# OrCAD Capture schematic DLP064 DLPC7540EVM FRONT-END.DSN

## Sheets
1 P05 - IMPORTANT NOTICE: rev: A.0
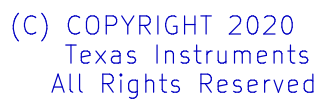
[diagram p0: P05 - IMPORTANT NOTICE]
2 P01 - TITLE
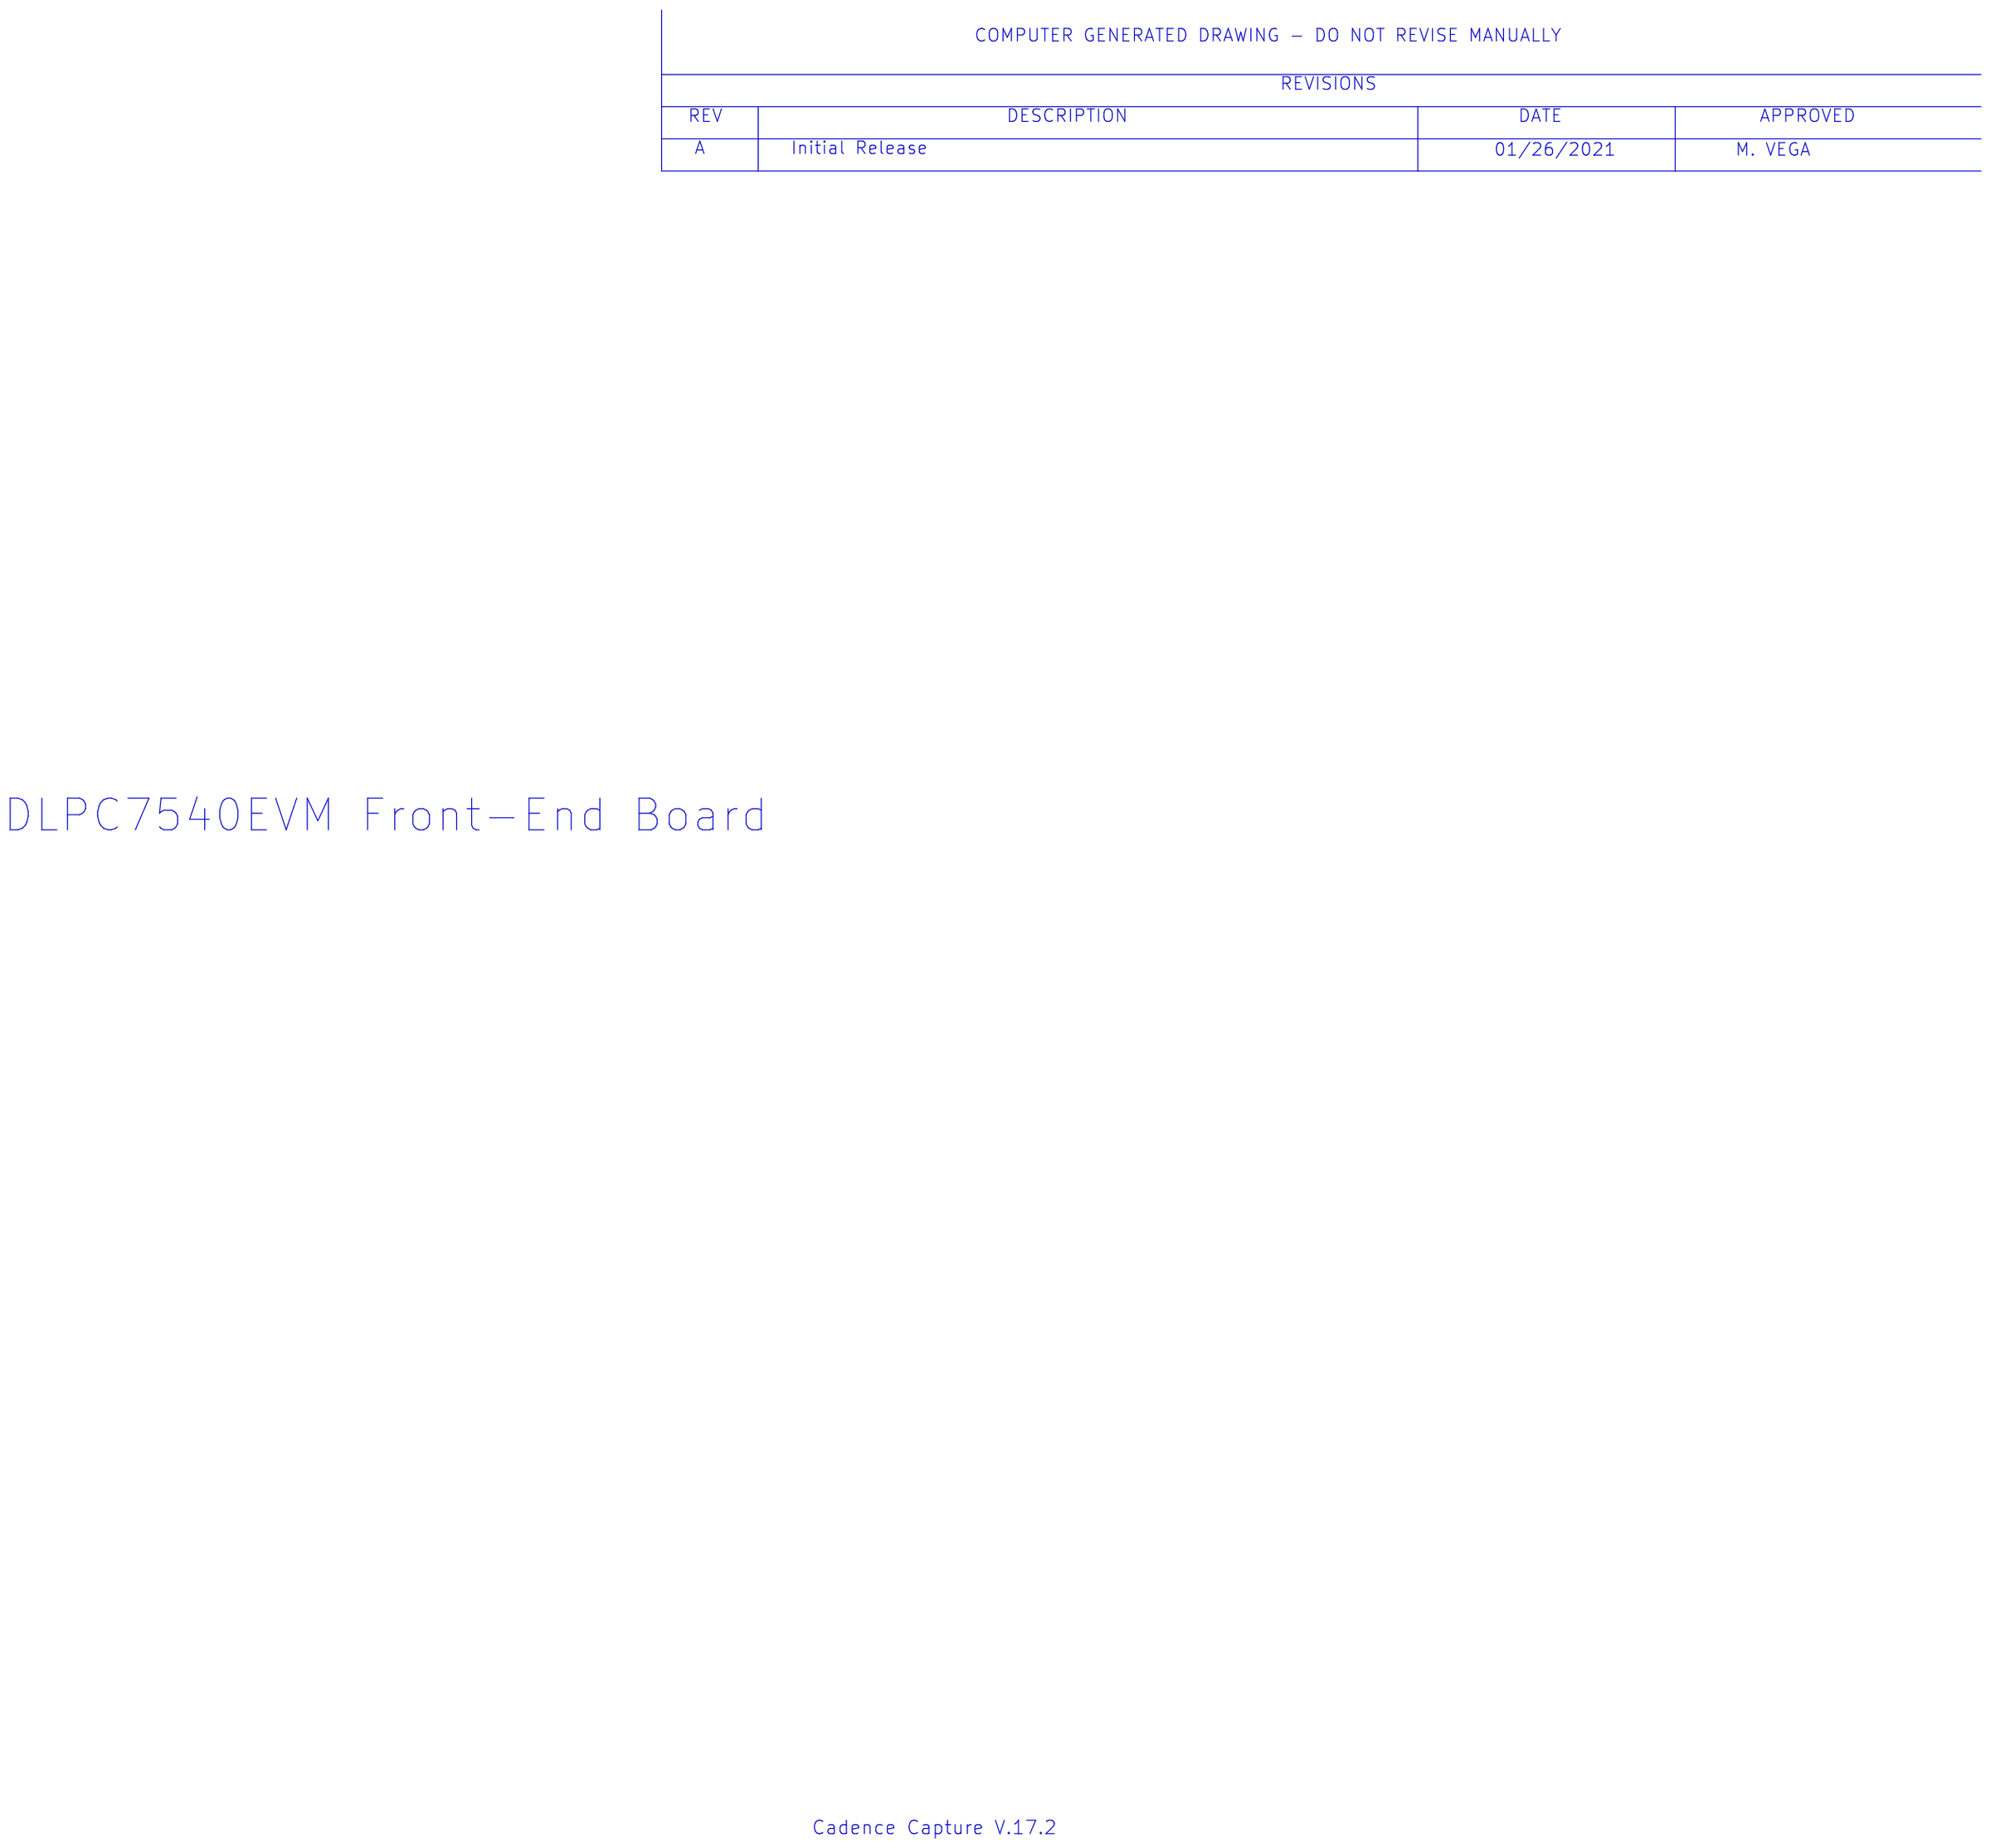
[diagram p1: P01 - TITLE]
3 P02 - IT6807: size A3
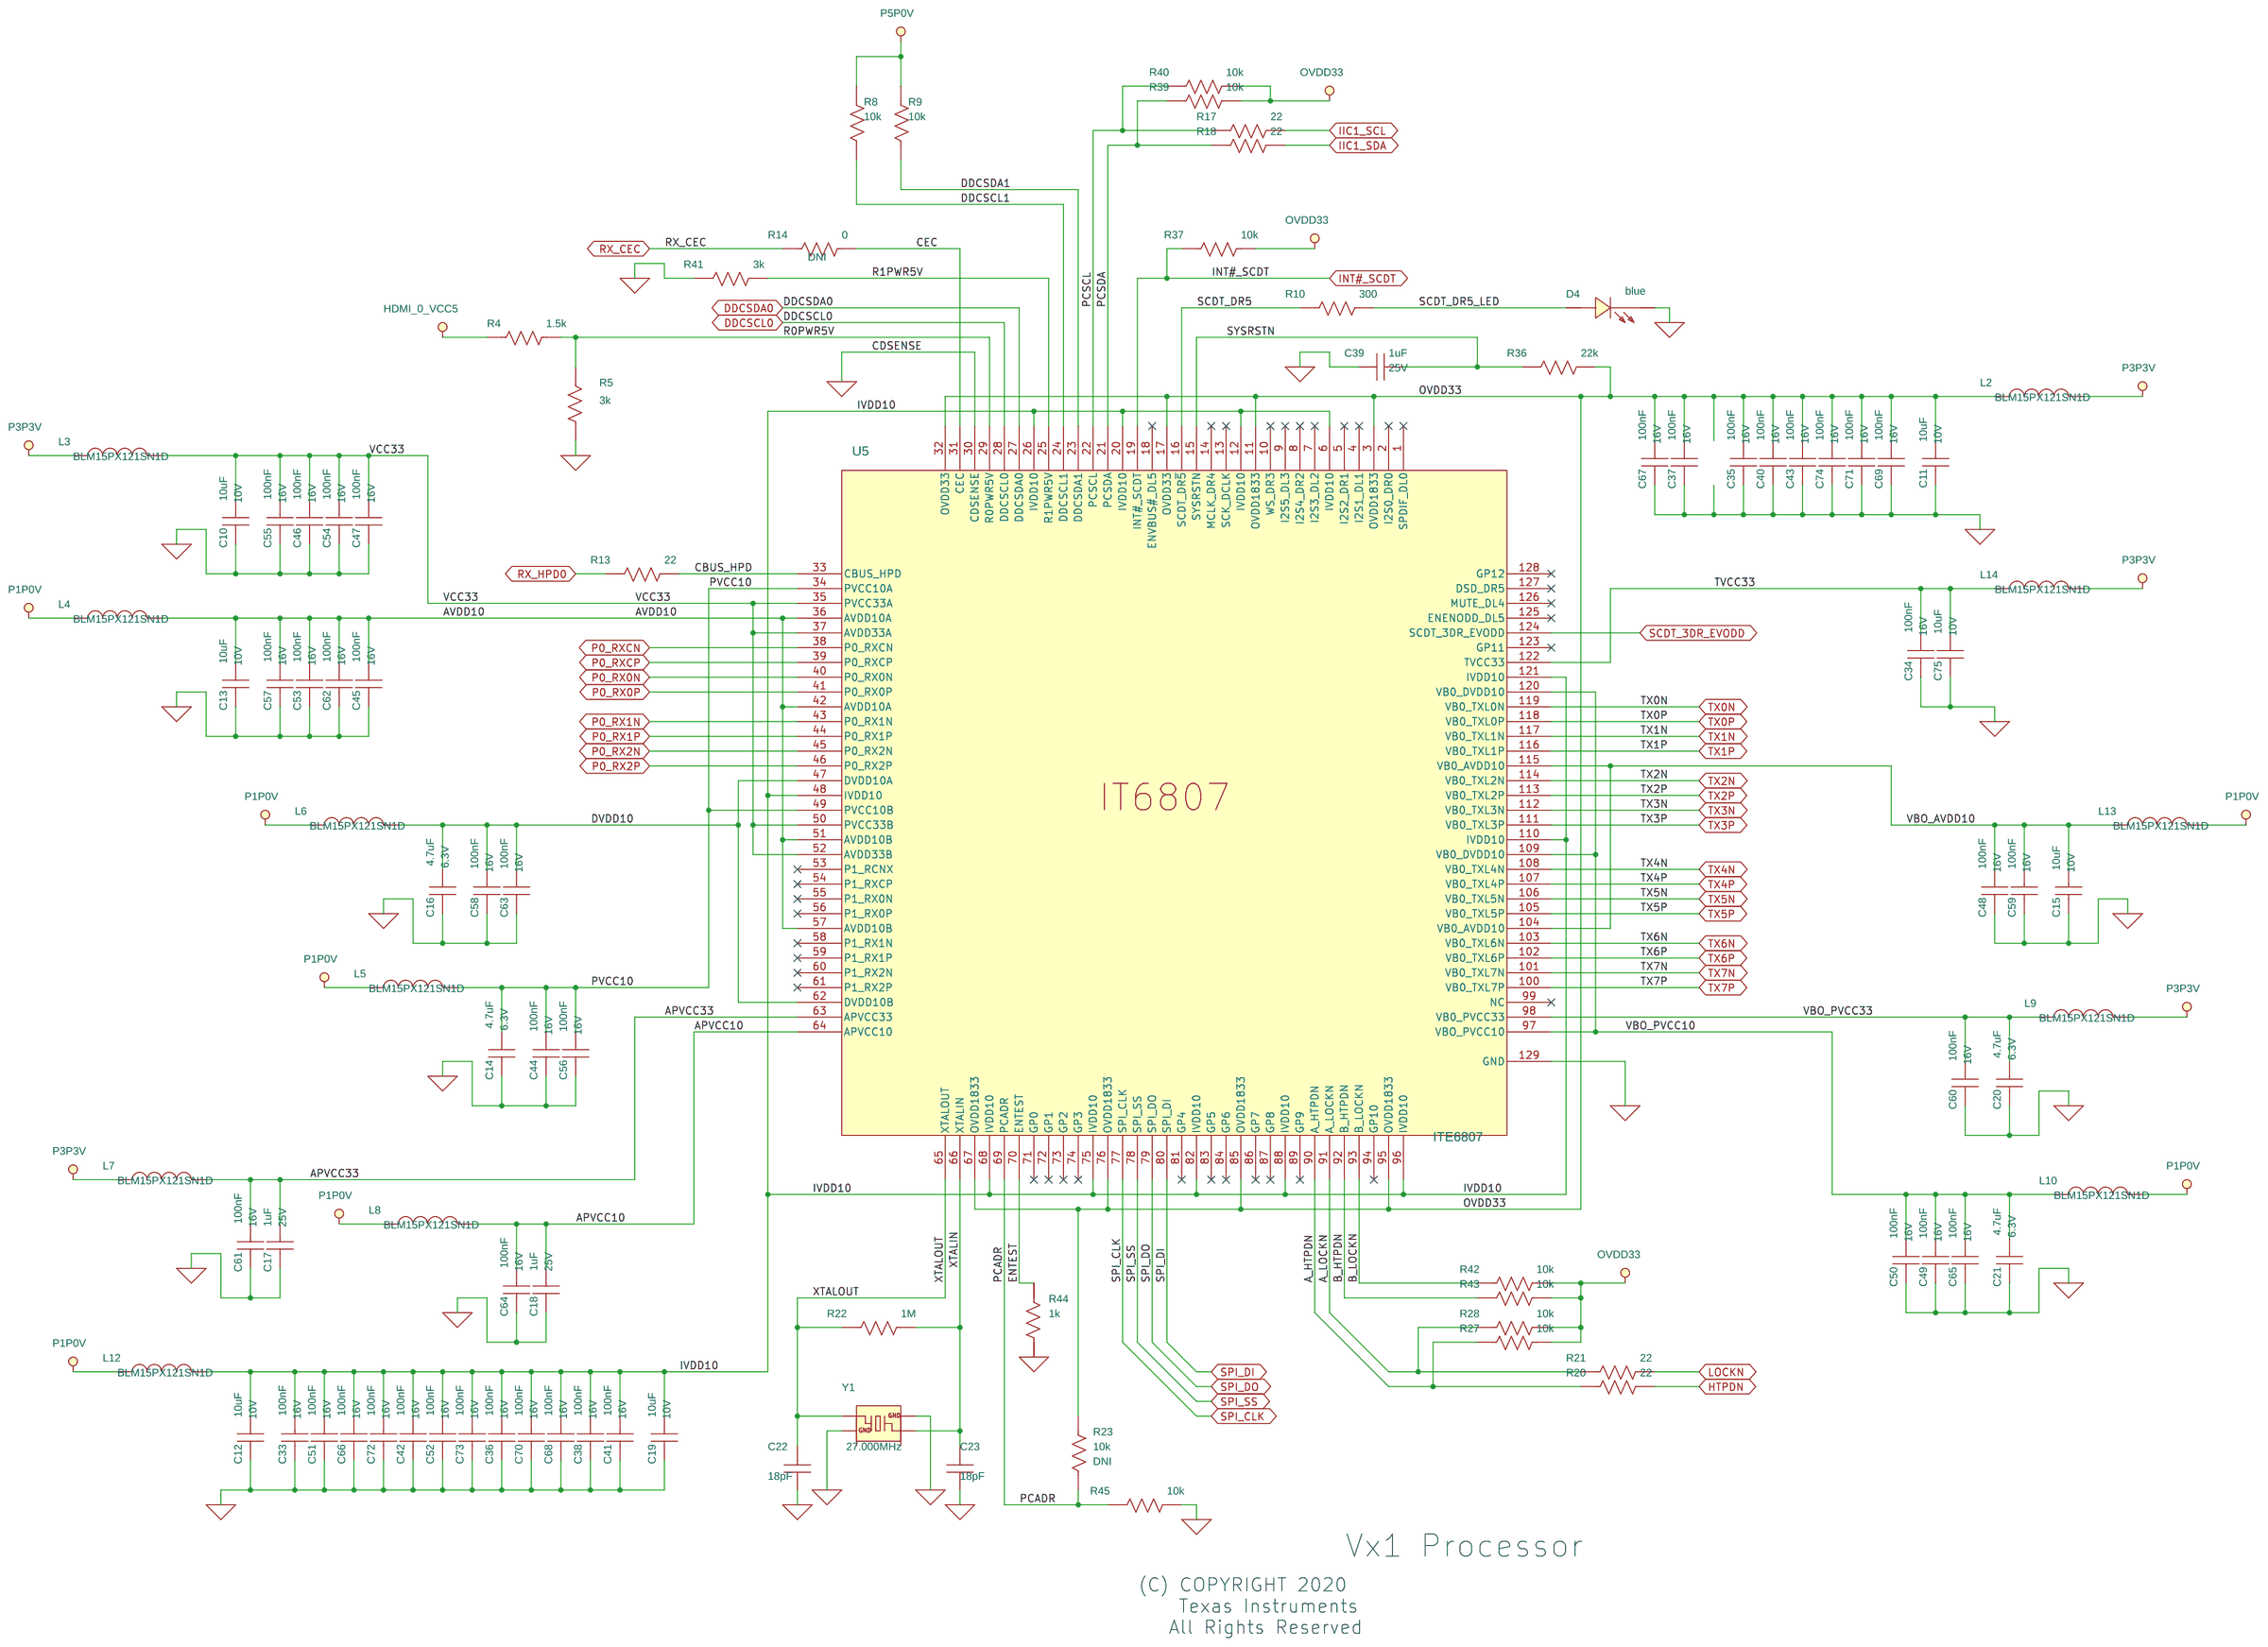
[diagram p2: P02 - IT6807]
4 P03 - HDMI & Vx1 Connection: size A3
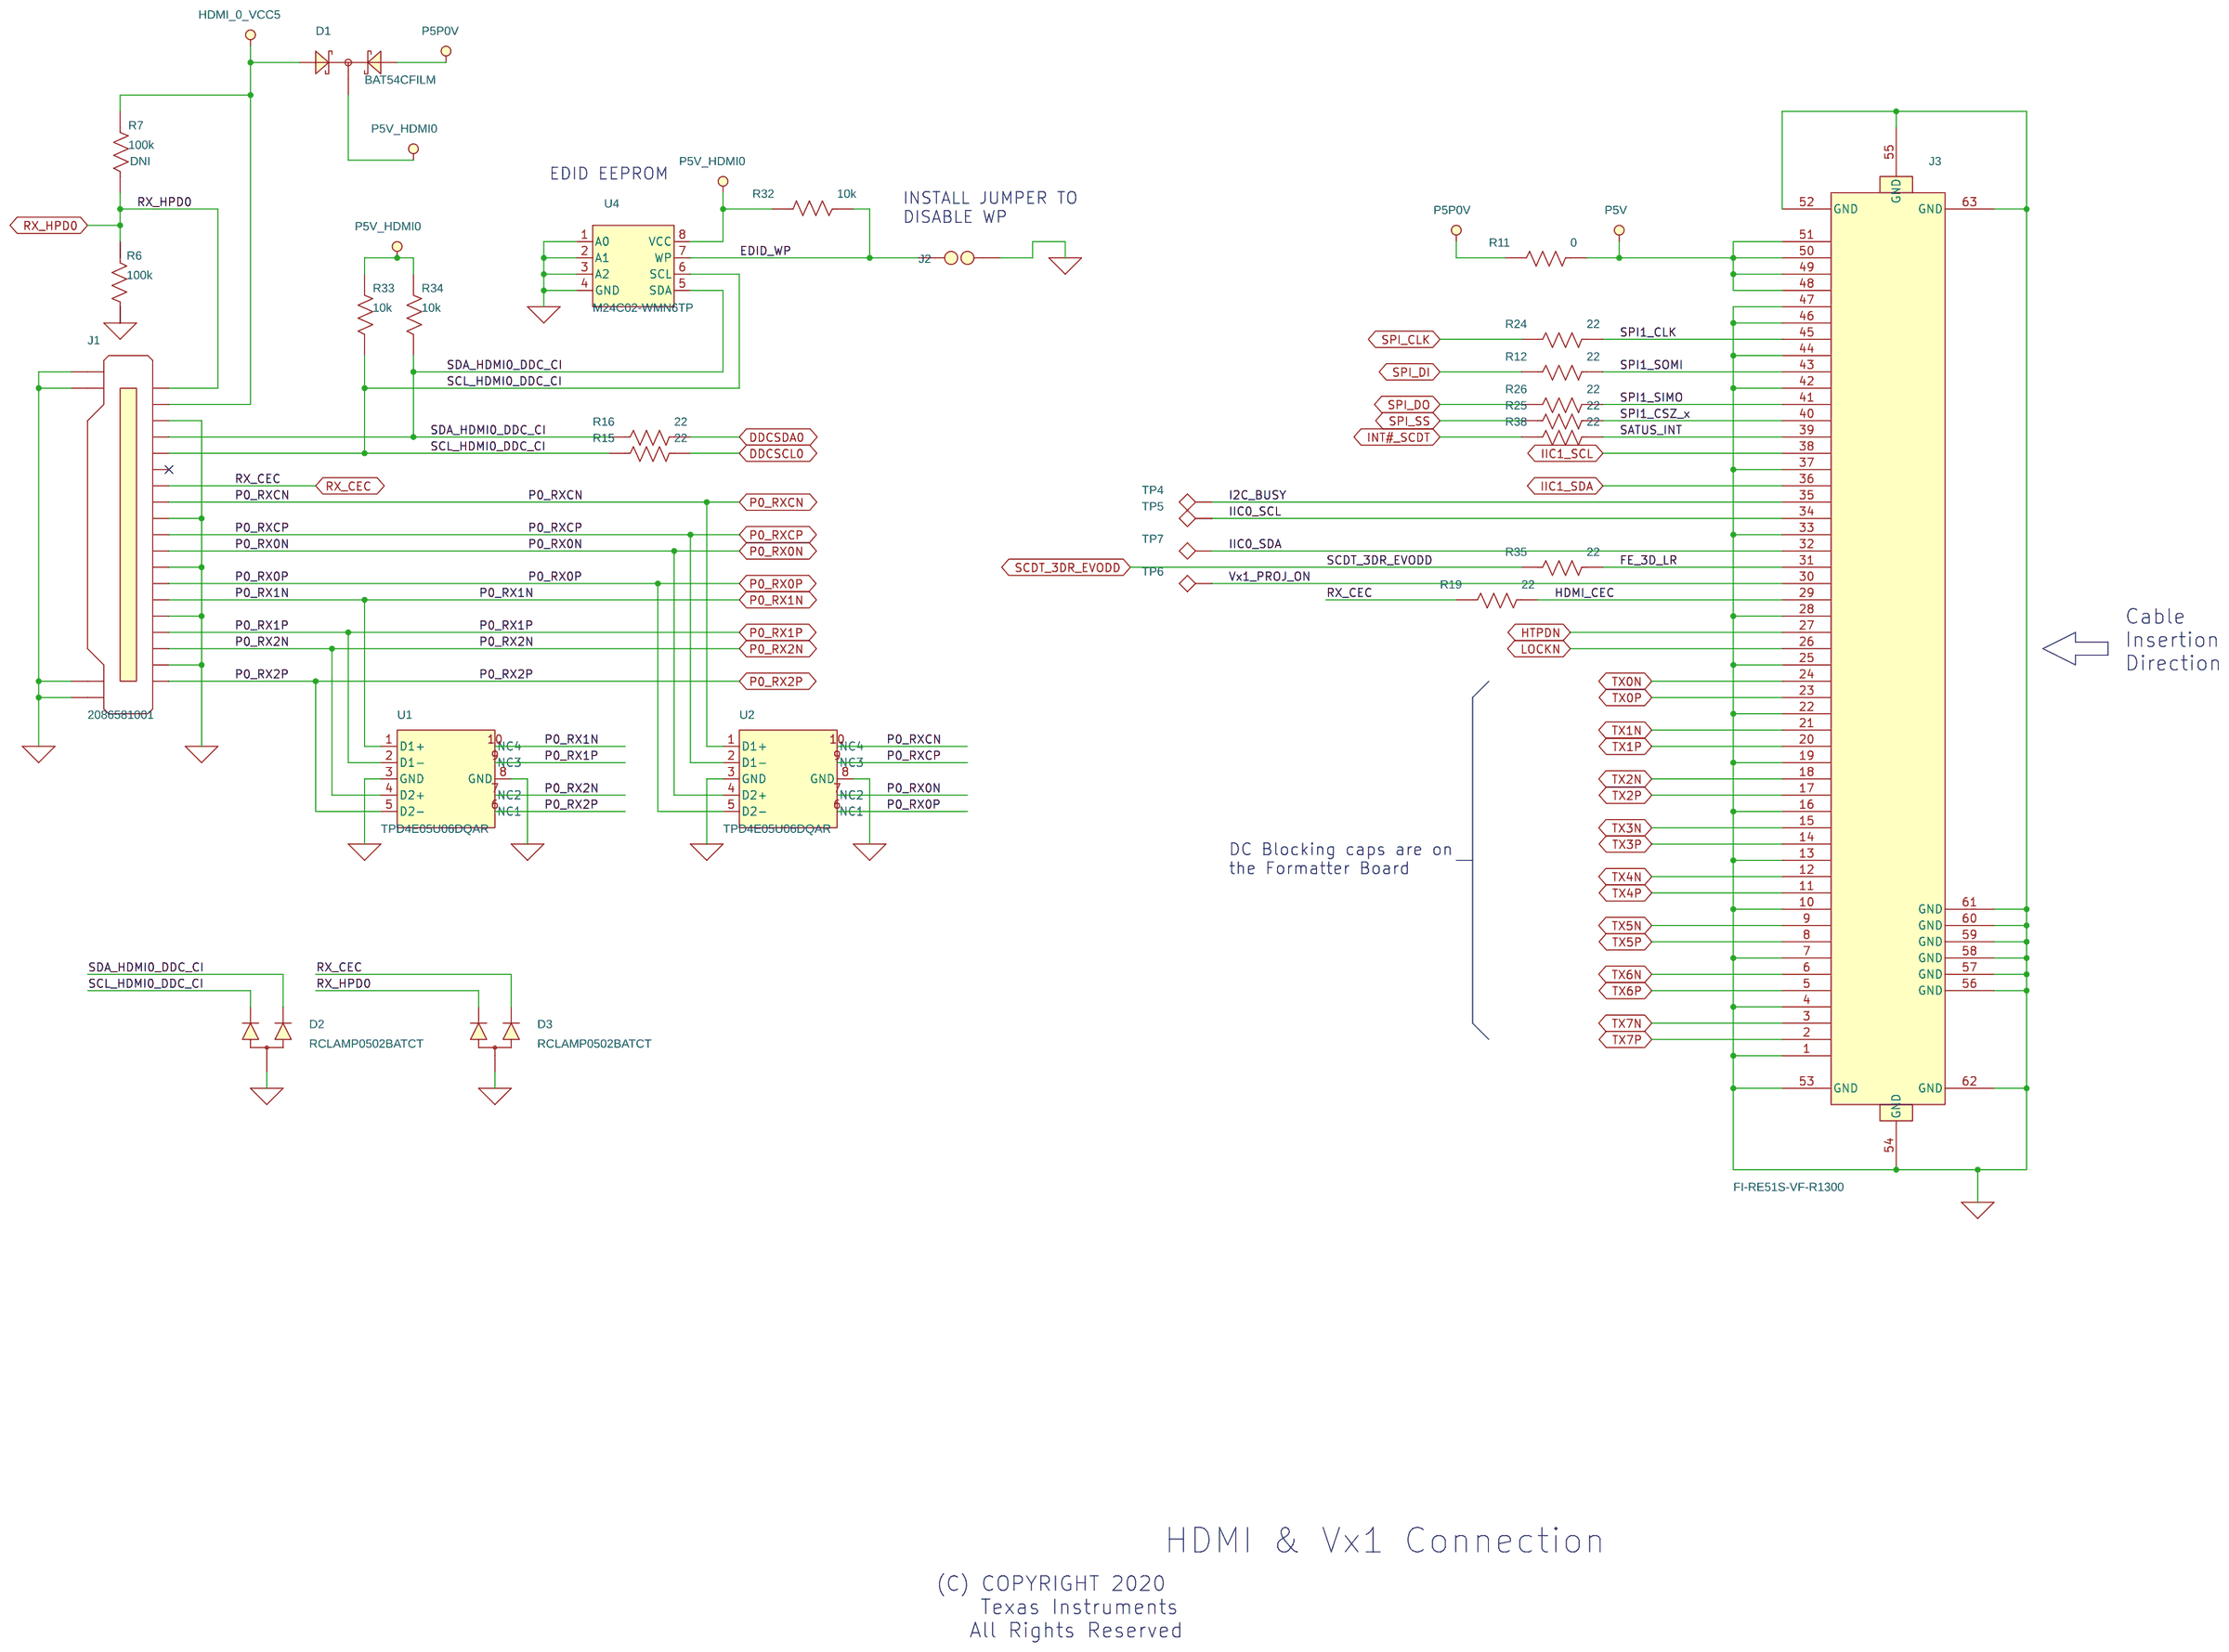
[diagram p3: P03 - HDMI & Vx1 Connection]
5 P04 - POWER: size A3
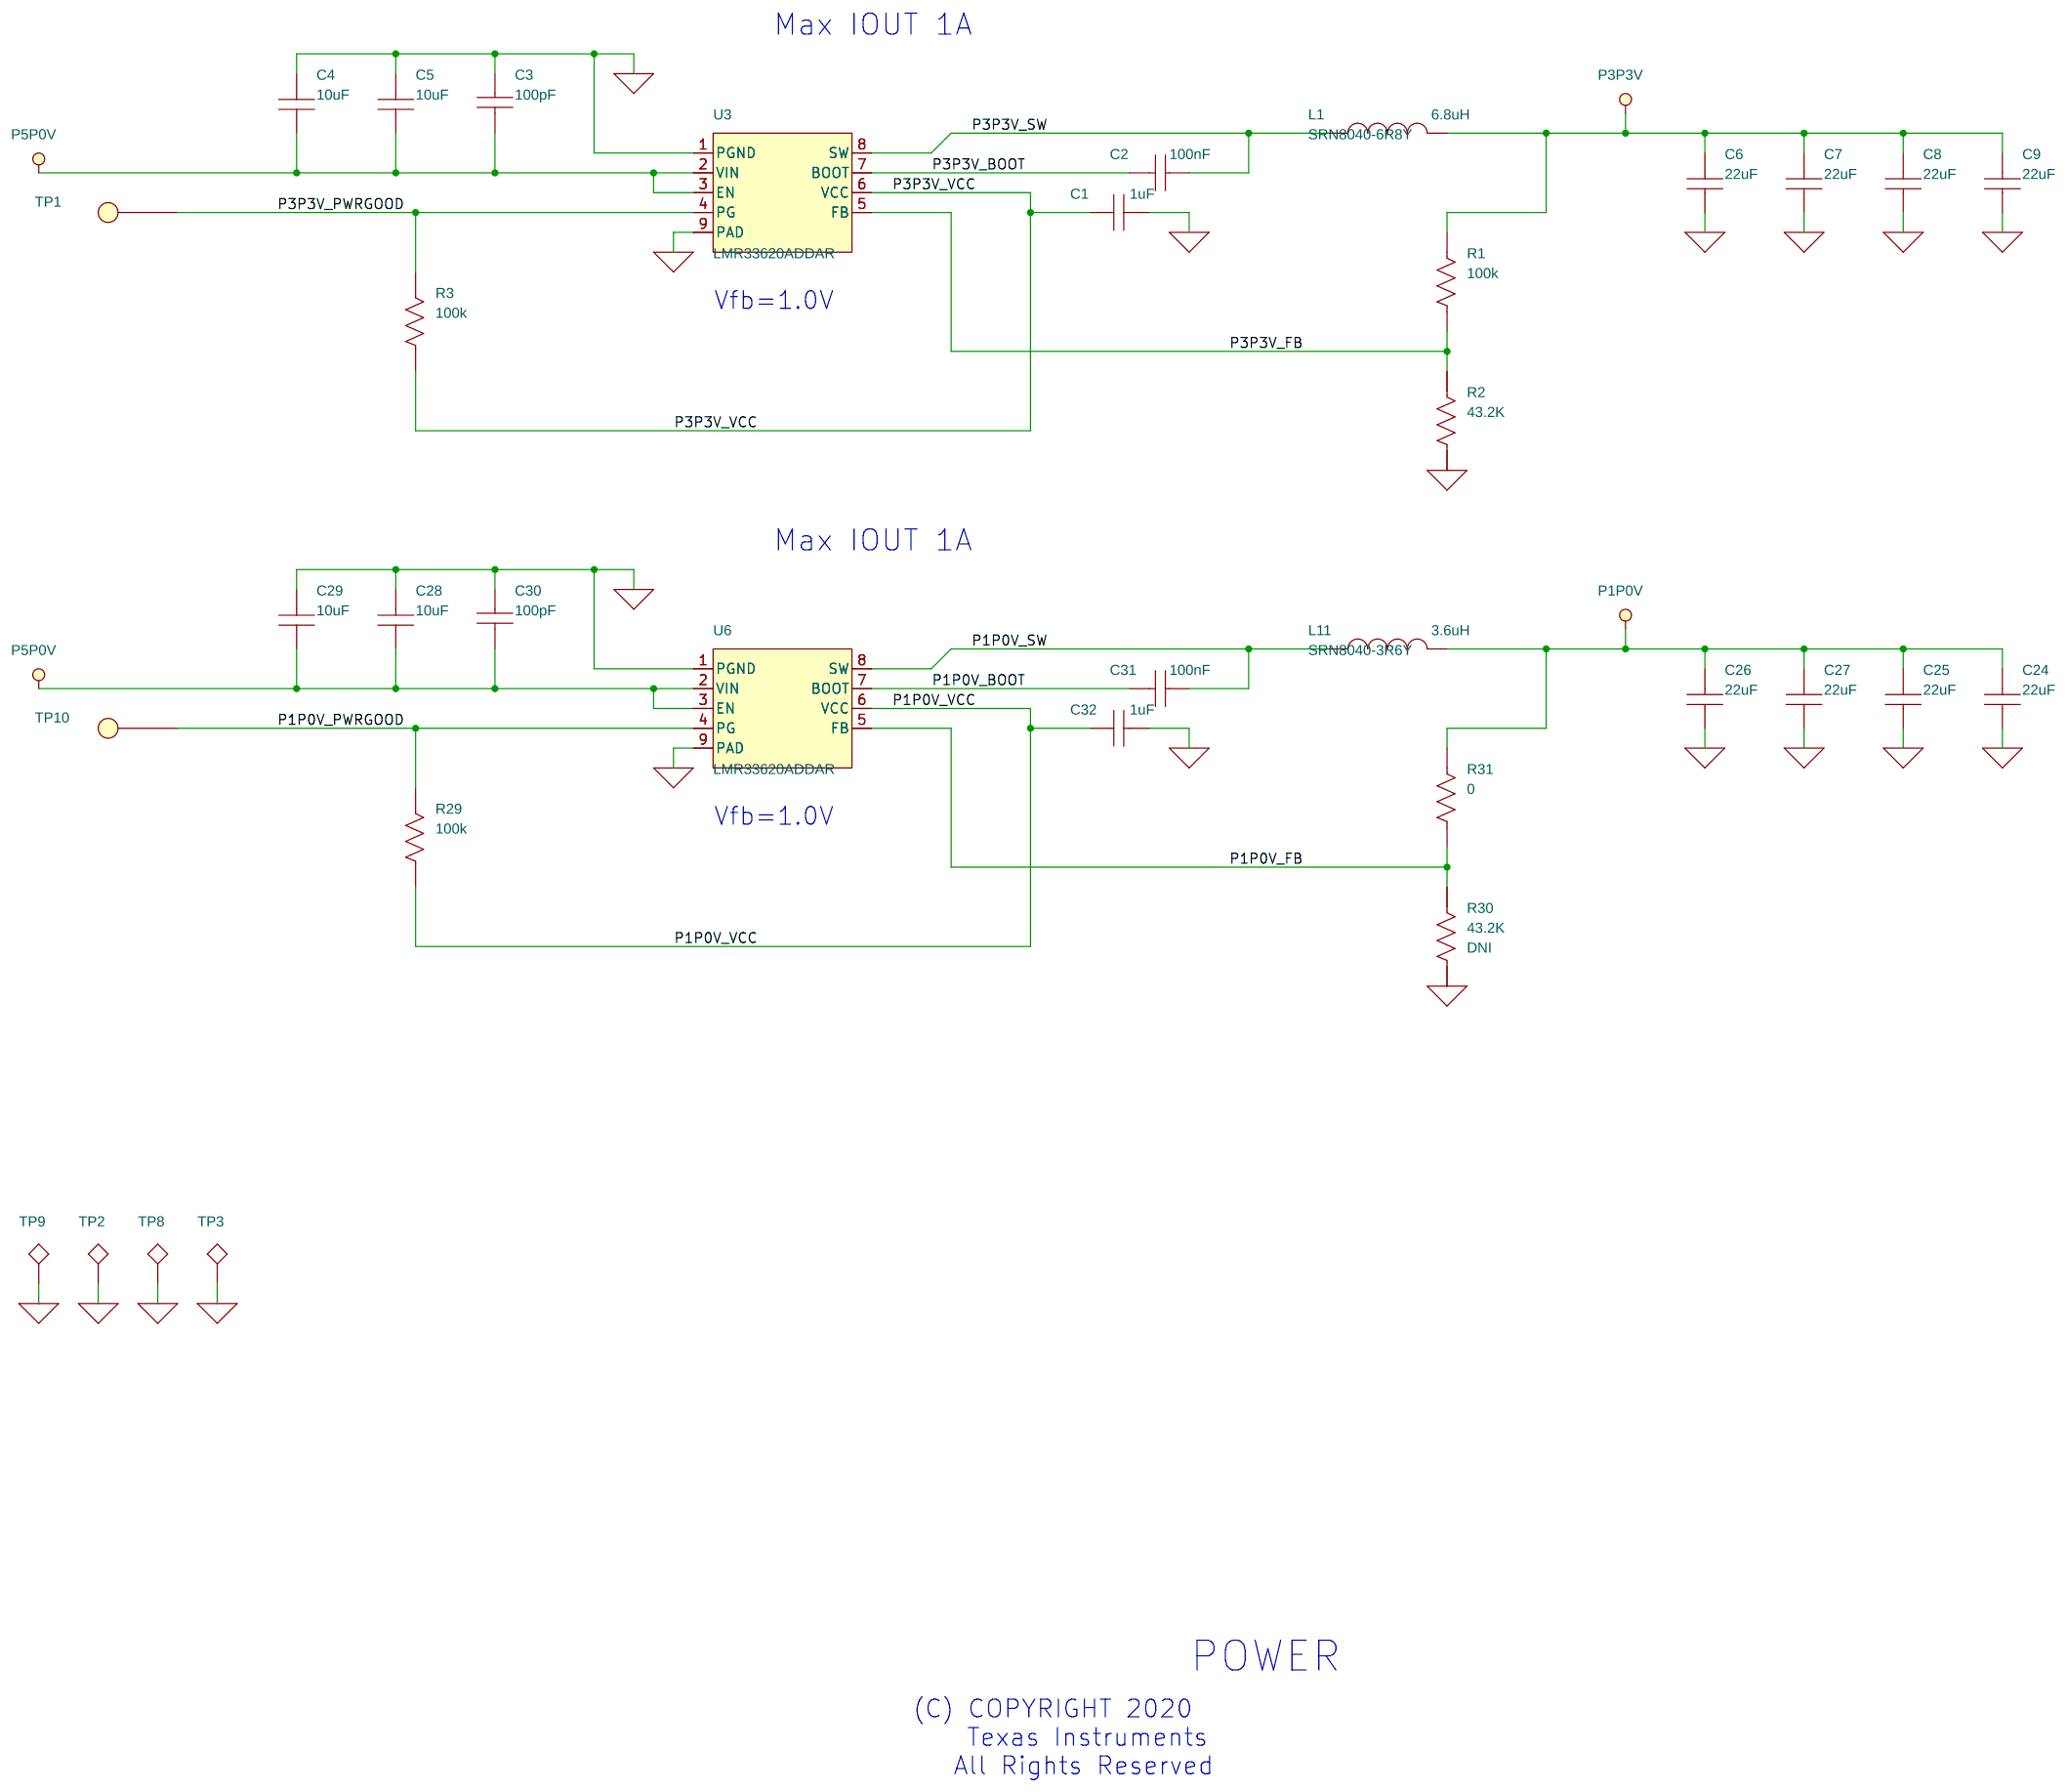
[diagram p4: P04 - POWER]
6 P06 - REVISIONS
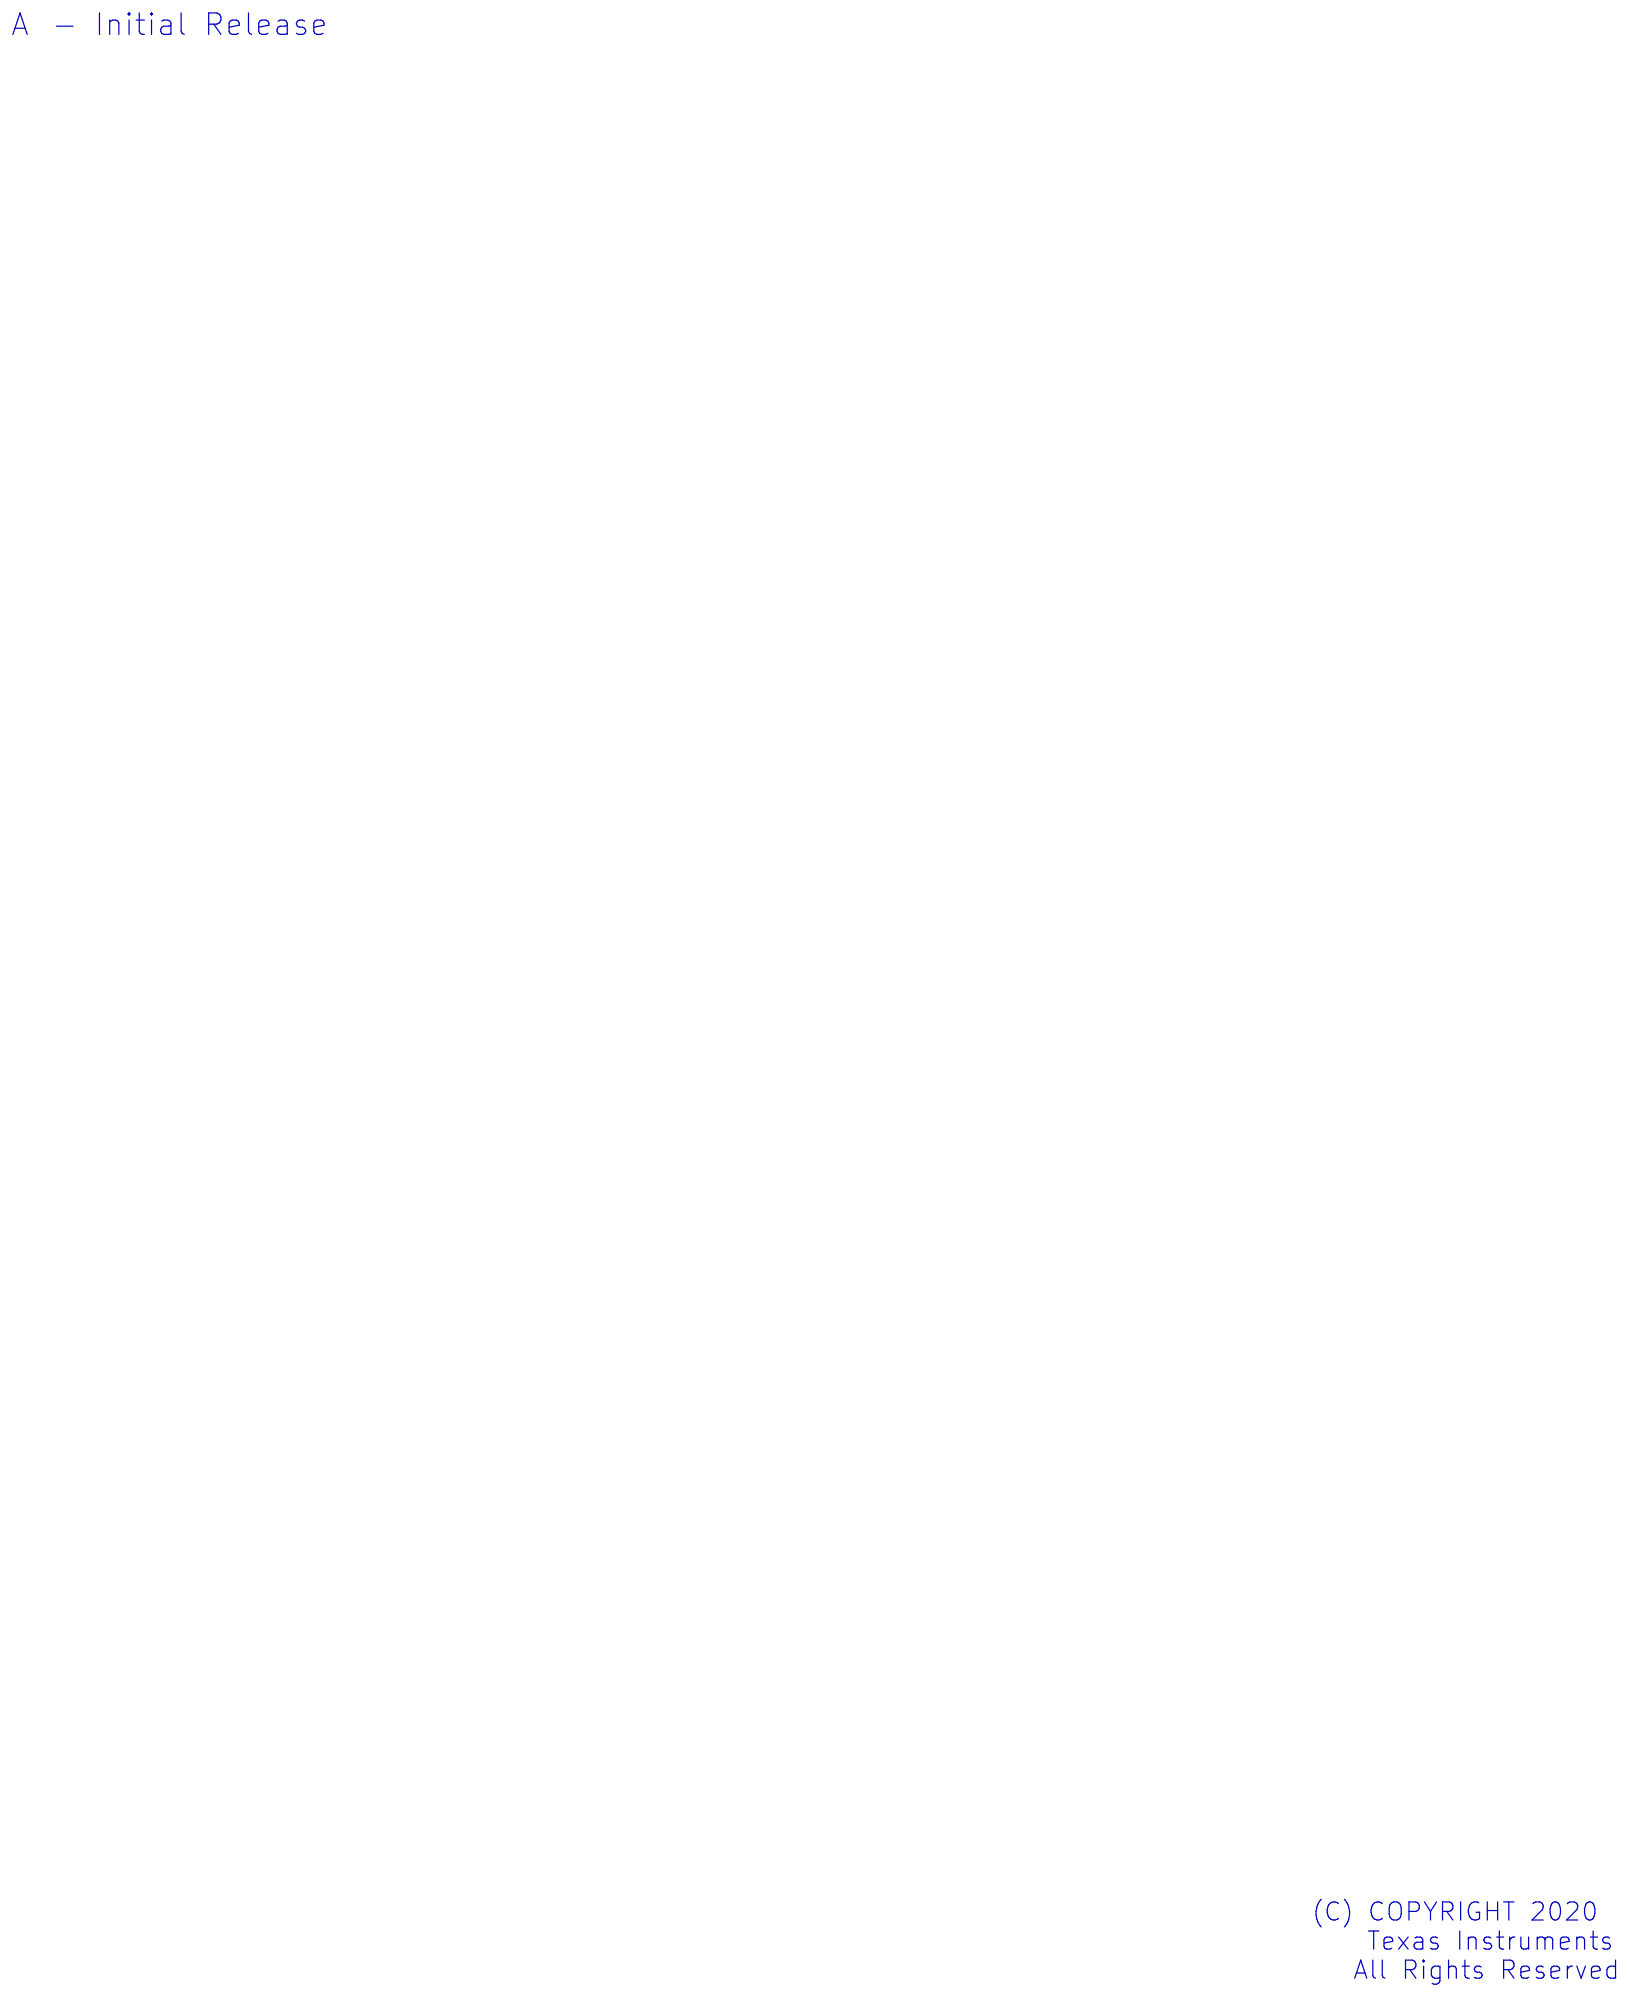
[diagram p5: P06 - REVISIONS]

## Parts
sheet P02 - IT6807
C10  10uF  [0603]
C11  10uF  [0603]
C12  10uF  [0603]
C13  10uF  [0603]
C14  4.7uF  [0402]
C15  10uF  [0603]
C16  4.7uF  [0402]
C17  1uF  [0402]
C18  1uF  [0402]
C19  10uF  [0603]
C20  4.7uF  [0402]
C21  4.7uF  [0402]
C22  18pF  [0402]
C23  18pF  [0402]
C33  100nF  [0402]
C34  100nF  [0402]
C35  100nF  [0402]
C36  100nF  [0402]
C37  100nF  [0402]
C38  100nF  [0402]
C39  1uF  [0402]
C40  100nF  [0402]
C41  100nF  [0402]
C42  100nF  [0402]
C43  100nF  [0402]
C44  100nF  [0402]
C45  100nF  [0402]
C46  100nF  [0402]
C47  100nF  [0402]
C48  100nF  [0402]
C49  100nF  [0402]
C50  100nF  [0402]
C51  100nF  [0402]
C52  100nF  [0402]
C53  100nF  [0402]
C54  100nF  [0402]
C55  100nF  [0402]
C56  100nF  [0402]
C57  100nF  [0402]
C58  100nF  [0402]
C59  100nF  [0402]
C60  100nF  [0402]
C61  100nF  [0402]
C62  100nF  [0402]
C63  100nF  [0402]
C64  100nF  [0402]
C65  100nF  [0402]
C66  100nF  [0402]
C67  100nF  [0402]
C68  100nF  [0402]
C69  100nF  [0402]
C70  100nF  [0402]
C71  100nF  [0402]
C72  100nF  [0402]
C73  100nF  [0402]
C74  100nF  [0402]
C75  10uF  [0603]
D4  blue  [LED-LTST-C190_LITEON]
L2  BLM15PX121SN1D  [0402]
L3  BLM15PX121SN1D  [0402]
L4  BLM15PX121SN1D  [0402]
L5  BLM15PX121SN1D  [0402]
L6  BLM15PX121SN1D  [0402]
L7  BLM15PX121SN1D  [0402]
L8  BLM15PX121SN1D  [0402]
L9  BLM15PX121SN1D  [0402]
L10  BLM15PX121SN1D  [0402]
L12  BLM15PX121SN1D  [0402]
L13  BLM15PX121SN1D  [0402]
L14  BLM15PX121SN1D  [0402]
R4  1.5k  [0402]
R5  3k  [0402]
R8  10k  [0402]
R9  10k  [0402]
R10  300  [0402]
R13  22  [0402]
R14  0  [0402]
R17  22  [0402]
R18  22  [0402]
R20  22  [0402]
R21  22  [0402]
R22  1M  [0402]
R23  10k  [0402]
R27  10k  [0402]
R28  10k  [0402]
R36  22k  [0402]
R37  10k  [0402]
R39  10k  [0402]
R40  10k  [0402]
R41  3k  [0402]
R42  10k  [0402]
R43  10k  [0402]
R44  1k  [0402]
R45  10k  [0402]
U5  ITE6807  [ITE6807_LQFP128]
Y1  27.000MHz  [Abracon_ABM8]
sheet P03 - HDMI & Vx1 Connection
D1  BAT54CFILM  [SOT-23-BAT54S_ST]
D2  RCLAMP0502BATCT  [Semtech_SC-75_SOT523]
D3  RCLAMP0502BATCT  [Semtech_SC-75_SOT523]
J1  2086581001  [Molex_47151-0001]
J2  HDR,2P,1R  [HDR2P_1R]
J3  FI-RE51S-VF-R1300  [FI-R51-HF_VF_Dual]
R6  100k  [0402]
R7  100k  [0402]
R11  0  [0805]
R12  22  [0402]
R15  22  [0402]
R16  22  [0402]
R19  22  [0402]
R24  22  [0402]
R25  22  [0402]
R26  22  [0402]
R32  10k  [0402]
R33  10k  [0402]
R34  10k  [0402]
R35  22  [0402]
R38  22  [0402]
TP4  TP_WHT  [TP_Keystone_5011]
TP5  TP_WHT  [TP_Keystone_5011]
TP6  TP_WHT  [TP_Keystone_5011]
TP7  TP_WHT  [TP_Keystone_5011]
U1  TPD4E05U06DQAR  [TPD4E05U06DQAR_USON10]
U2  TPD4E05U06DQAR  [TPD4E05U06DQAR_USON10]
U4  M24C02-WMN6TP  [SOIC-8_3p90mm_wide]
sheet P04 - POWER
C1  1uF  [0402]
C2  100nF  [0402]
C3  100pF  [0402]
C4  10uF  [1210]
C5  10uF  [1210]
C6  22uF  [0805]
C7  22uF  [0805]
C8  22uF  [0805]
C9  22uF  [0805]
C24  22uF  [0805]
C25  22uF  [0805]
C26  22uF  [0805]
C27  22uF  [0805]
C28  10uF  [1210]
C29  10uF  [1210]
C30  100pF  [0402]
C31  100nF  [0402]
C32  1uF  [0402]
L1  6.8uH  [Bourns_SRN8040]
L11  3.6uH  [Bourns_SRN8040]
R1  100k  [0402]
R2  43.2K  [0402]
R3  100k  [0402]
R29  100k  [0402]
R30  43.2K  [0402]
R31  0  [0402]
TP1  TP_WHT  [TP_Keystone_5011]
TP2  TP_BLK  [TP_Keystone_5011]
TP3  TP_BLK  [TP_Keystone_5011]
TP8  TP_BLK  [TP_Keystone_5011]
TP9  TP_BLK  [TP_Keystone_5011]
TP10  TP_WHT  [TP_Keystone_5011]
U3  LMR33620ADDAR  [HSOIC8_DDA0008J]
U6  LMR33620ADDAR  [HSOIC8_DDA0008J]

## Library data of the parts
C10-C13 C15 C19 C75 = PAS,CAP,NP: CCA: 34; DigiKey: 445-6853-1-ND; Family: passive; Index PN: 1207; Install: Y; Lead Style: SMT; MFG: TDK; P/D_NUM: C1608X5R1A106M080AC; Part Number: C1608X5R1A106M080AC; Part Specific: CAP CER 10UF 10V 20% X5R 0603; TOLERANCE: 20%; Type: capacitor; VPC: 10V; Vendor: TDK
C14 C16 C20 C21 = PAS,CAP,NP: ALT_SYMBOLS: 0402_1mm; DigiKey: 490-5915-1-ND; Family: passive; Index PN: 1389; Lead Style: SMT; MFG: Murata; Material: x5r; P/D_NUM: GRM155R60J475ME47D; Part Number: GRM155R60J475ME47D; Part Specific: CAP CER 4.7UF 6.3V 20% X5R 0402; Tolerance: 20%; VPC: 6.3V; Vendor: Murata
C1 C17 C18 C32 C39 = PAS,CAP,NP: ALT_SYMBOLS: 0402_1mm; DigiKey: 1276-1445-1-ND; Family: passive; Index PN: 1278; Lead Style: SMT; MFG: Samsung; P/D_NUM: CL05A105KA5NQNC; Part Number: CL05A105KA5NQNC; Part Specific: CAP CER 1UF 25V 20% X5R 0402; Tolerance: 20%; VPC: 25V; Vendor: Samsung
C22 C23 = PAS,CAP,NP: ALT_SYMBOLS: 0402_1mm; DigiKey: 311-1415-1-ND; Family: passive; Lead Style: SMT; MFG: Yageo; Material: npo; P/D_NUM: CC0402JRNPO9BN180; Part Number: CC0402JRNPO9BN180; Part Specific: CAP CER 18PF 50V C0G 5% 0402; Tolerance: 5%; VPC: 50V; Vendor: Yageo; Voltage: 50V
C33-C38 C40-C74 = PAS,CAP,NP: ALT_SYMBOLS: 0402_1mm; DigiKey: 1276-1001-1-ND; Family: passive; Index PN: 681; Lead Style: SMT; MFG: Samsung; Material: x7r; P/D_NUM: CL05B104KO5NNNC; Part Number: CL05B104KO5NNNC; Part Specific: CAP CER .1UF 16V X7R 0402; Tolerance: 10%; VPC: 16V; Vendor: Samsung
D4 = PAS,DIODE,LED,ALT: DigiKey: 160-1647-1-ND; Family: passive; Index PN: 1728; Install: Y; Lead Style: SMT; MFG: Liteon; P/D_NUM: LTST-C191TBKT; Part Number: LTST-C191TBKT; Part Specific: LED BLUE CLEAR CHIP SMD; Type: diode,led; Vendor: Liteon
L2-L10 L12-L14 = PAS,INDUCTOR: ALT_SYMBOLS: 0402_1mm; DigiKey: 490-9656-1-ND; Family: passive; Index PN: 1670; Lead Style: SMT; MFG: Murata; Part Specific: FERRITE BEAD 120 OHM 0402 2A 50Ohm DC; Type: ferrite bead; VPC: 2000mA; Vendor: Murata
R4 = PAS,R,large: ALT_SYMBOLS: 0402_1mm; DigiKey: P1.50KLCT-ND; Family: passive; Index PN: 1117; Lead Style: SMT; MFG: Panasonic; Material: chip; P/D_NUM: ERJ-2RKF1501X; Part Number: ERJ-2RKF1501X; Part Specific: RES 1.50K OHM 1/10W 1% 0402 SMD; Tolerance: 1%; Type: resistor; Vendor: Panasonic
R5 R41 = PAS,R,large: ALT_SYMBOLS: 0402_1mm; DigiKey: P3.00KLCT-ND; Family: passive; Index PN: 1230; Lead Style: SMT; MFG: Panasonic; P/D_NUM: ERJ-2RKF3001X; Part Number: ERJ-2RKF3001X; Part Specific: RES 3K OHM 1/10W 1% 0402 SMD; Tolerance: 1%; Type: resistor; Vendor: Panasonic
R8 R9 R27 R28 R32-R34 R37 R39 R40 R42 R43 R45 = PAS,R,large: ALT_SYMBOLS: 0402_1mm; DigiKey: 311-10.0KLRCT-ND; Family: passive; Index PN: 680; Lead Style: SMT; MFG: Yageo; Material: chip; P/D_NUM: RC0402FR-0710KL; Part Number: RC0402FR-0710KL; Part Specific: RES SMD 10K OHM 1% 1/16W 0402; Power: 1/16W; Tolerance: 1%; Type: resistor; VPC: 1/16W; Vendor: Yageo
R10 = PAS,R,large: ALT_SYMBOLS: 0402_1mm; DigiKey: P300LCT-ND; Family: passive; Index PN: 1053; Lead Style: SMT; MFG: Panasonic; Material: chip; P/D_NUM: ERJ-2RKF3000X; Part Number: ERJ-2RKF3000X; Part Specific: RES 300 OHM 1/10W 1% 0402 SMD; Tolerance: 1%; Type: resistor; VPC: 1/16W; Vendor: Panasonic
R12 R13 R15-R21 R24-R26 R35 R38 = PAS,R,large: ALT_SYMBOLS: 0402_1mm; DigiKey: 311-22.0LRCT-ND; Family: passive; Index PN: 1215; Lead Style: SMT; MFG: Yageo; Material: chip; P/D_NUM: RC0402FR-0722RL; Part Number: RC0402FR-0722RL; Part Specific: RES 22.0 OHM 1/16W 1% 0402 SMD; Tolerance: 1%; Type: resistor; VPC: 1/16W; Vendor: Yageo
R14 = PAS,R,large: ALT_SYMBOLS: 0402_1mm; DigiKey: P0.0JCT-ND; Family: passive; Index PN: 687; Install: DNI; Lead Style: SMT; MFG: Panasonic; Material: chip; P/D_NUM: ERJ-2GE0R00X; Part Number: ERJ-2GE0R00X; Part Specific: RES 0.0 OHM 1/16W 0402 SMD; Power: 1/16W; Type: resistor; VPC: 1/16W; Vendor: Panasonic
R22 = PAS,R,large: ALT_SYMBOLS: 0402_1mm; DigiKey: P1.00MLCT-ND; Family: passive; Index PN: 1229; Lead Style: SMT; MFG: Panasonic; Material: chip; P/D_NUM: ERJ-2RKF1004X; Part Number: ERJ-2RKF1004X; Part Specific: RES 1M OHM 1/10W 1% 0402 SMD; Tolerance: 1%; Type: resistor; Vendor: Panasonic
R23 = PAS,R,large: ALT_SYMBOLS: 0402_1mm; DigiKey: 311-10.0KLRCT-ND; Family: passive; Index PN: 680; Install: DNI; Lead Style: SMT; MFG: Yageo; Material: chip; P/D_NUM: RC0402FR-0710KL; Part Number: RC0402FR-0710KL; Part Specific: RES SMD 10K OHM 1% 1/16W 0402; Power: 1/16W; Tolerance: 1%; Type: resistor; VPC: 1/16W; Vendor: Yageo
R36 = PAS,R,large: ALT_SYMBOLS: 0402_1mm; DigiKey: YAG4356CT-ND; Family: passive; Index PN: 1686; Lead Style: SMT; MFG: Yageo; Material: chip; P/D_NUM: RT0402BRE0722KL; Part Number: RT0402BRE0722KL; Part Specific: RES SMD 22K OHM 0.1% 1/16W 0402; Tolerance: 0.1%; Type: resistor; VPC: 1/16W; Vendor: Yageo
R44 = PAS,R,large: ALT_SYMBOLS: 0402_1mm; DigiKey: 311-1.00KLRCT-ND; Family: passive; Index PN: 684; Lead Style: SMT; MFG: Yageo; Material: chip; P/D_NUM: RC0402FR-071KL; Part Number: RC0402FR-071KL; Part Specific: RES 1.00K OHM 1/10W 1% 0402 SMD; Power: 1/16W; Tolerance: 1%; Type: resistor; VPC: 1/16W; Vendor: Yageo
U5 = INF,VIDEO,IT6807_LQFP-128_0: DigiKey: ---; Family: interface; Index PN: 1774; Lead Style: SMT; MFG: ITE Tech Inc; P/D_NUM: IT6807E; Part Number: IT6807E; Part Specific: HDMI RCVR Vx1 OUT 128LQFP; Type: video; Vendor: ITE Tech Inc
Y1 = PAS,CRYSTAL,ABM11: DigiKey: 535-9141-1-ND; Family: passive; Index PN: 1231; Lead Style: SMT; MFG: Abracon; P/D_NUM: ABM8-27.000MHZ-B2-T; Part Number: ABM8-27.000MHZ-B2-T; Part Specific: CRYSTAL 27MHZ 18PF SMD; Vendor: Abracon
D1 = PAS,DIODE,SCHOTTKY,BAT54CFILM: DigiKey: 497-3786-1-ND; Family: passive; Index PN: 1514; Lead Style: SMT; MFG: STMicroelectronics; Part Specific: DIODE ARRAY SCHOTTKY 40V SOT23-3; Type: diode,schottky; VPC: 40V; Vendor: STMicroelectronics
D2 D3 = PAS,DIODE,TVS,RClamp502b,small: DigiKey: RCLAMP0502BATCTCT-ND; Family: passive; Index PN: 1222; Lead Style: SMT; MFG: Semtech; Part Specific: TVS DIODE 5V 25V SC75; Type: diode,tvs; Vendor: Semtech
J1 = EM,CONN,HDMI,1R,x1: DigiKey: 900-2086581001CT-ND; Family: electro/mechanical; Lead Style: SMT; MFG: Molex; Part Specific: CONN RCPT HDMI V2.1 19POS SMD RA; Type: connector; Vendor: Molex
J2 = EM,JMP,2P,1R: DigiKey: 952-2261-ND; Index PN: 180; Lead Style: TH; MFG: Harwin; P/D_NUM: M20-9990245; Part Number: M20-9990245; Part Specific: CONN HEADER VERT 2POS 2.54MM; Pin Cnt: 2; Pin Spacing: 100mil; Row Cnt: 1; Type: header; Vendor: Harwin
J3 = TMP_094452: DigiKey: 670-2149-1-ND; Family: electro/mechanical; Index PN: 1629; Lead Style: SMT; MFG: JAE; Part Specific: CONN RCPT 51POS 0.02 GOLD SMD; Pin Cnt: 51; Type: connector; Vendor: JAE
R6 = PAS,R,large: ALT_SYMBOLS: 0402_1mm; DigiKey: 541-100KLCT-ND; Family: passive; Index PN: 712; Lead Style: SMT; MFG: Vishay/Dale; Material: chip; P/D_NUM: CRCW0402100KFKED; Part Number: CRCW0402100KFKED; Part Specific: RES 100K OHM 1/10W 1% 0402 SMD; Power: 1/16W; Tolerance: 1%; Type: resistor; VPC: 1/16W; Vendor: Vishay/Dale
R7 = PAS,R,large: ALT_SYMBOLS: 0402_1mm; DigiKey: 541-100KLCT-ND; Family: passive; Index PN: 712; Install: DNI; Lead Style: SMT; MFG: Vishay/Dale; Material: chip; P/D_NUM: CRCW0402100KFKED; Part Number: CRCW0402100KFKED; Part Specific: RES 100K OHM 1/10W 1% 0402 SMD; Power: 1/16W; Tolerance: 1%; Type: resistor; VPC: 1/16W; Vendor: Vishay/Dale
R11 = PAS,R,large: DigiKey: P0.0ACT-ND; Family: passive; Index PN: 160; MFG: Panasonic; Material: chip; P/D_NUM: ERJ-6GEY0R00V; Part Number: ERJ-6GEY0R00V; Part Specific: RES 0.0 OHM 1/8W 0805 SMD 2A; Power: 1/8w; Type: resistor; VPC: 2A; Vendor: Panasonic
TP4-TP7 = EM,TERM,TESTPOINT: DigiKey: 36-5012-ND; Family: electro/mechanical; Index PN: 1162; Install: DNI; Lead Style: TH; MFG: Keystone; P/D_NUM: 5012; Part Number: 5012; Part Specific: TEST POINT PC MULTI PURPOSE WHT .063inD hole; Type: terminal; Vendor: Keystone
U1 U2 = PAS,DIODE,ARRAY,TVS,TPD4E05U06: DigiKey: 296-35765-1-ND; Family: passive; Index PN: 1775; Lead Style: SMT; MFG: Texas Instruments; Part Specific: TVS DIODE 5.5V 14V 10SON; Type: diode,tvs; Vendor: Texas Instruments
U4 = MEM,EEPROM,24LCxx: DigiKey: 497-8552-1-ND; Family: memory; Index PN: 1131; Lead Style: SMT; MFG: Stmicroelectronics; Part Specific: IC EEPROM 2KBIT 400KHZ 8SOIC; Type: eeprom; Vendor: Stmicroelectronics
C2 C31 = PAS,CAP,NP: ALT_SYMBOLS: 0402_1mm; DigiKey: 587-3499-1-ND; Family: passive; Index PN: 1280; Lead Style: SMT; MFG: Taiyo Yuden; Material: x5r; P/D_NUM: UMK105BJ104KV-F; Part Number: UMK105BJ104KV-F; Part Specific: CAP CER 0.1UF 50V 10% X5R 0402; Tolerance: 10%; VPC: 50V; Vendor: Taiyo Yuden
C3 C30 = PAS,CAP,NP: ALT_SYMBOLS: 0402_1mm; DigiKey: 478-1089-1-ND; Family: passive; Index PN: 1220; Lead Style: SMT; MFG: AVX; Material: x7r; P/D_NUM: 04025C101KAT2A; Part Number: 04025C101KAT2A; Part Specific: CAP CER 100PF 50V 10% X7R 0402; Tolerance: 10%; VPC: 50V; Vendor: AVX
C4 C5 C28 C29 = PAS,CAP,NP: DigiKey: 445-8914-1-ND; Family: passive; Index PN: 1601; Install: Y; Lead Style: SMT; MFG: TDK; Material: x7s; P/D_NUM: C3225X7S1H106K250AE; Part Number: C3225X7S1H106K250AE; Part Specific: CAP CER 10UF 50V 10% X7S 1210; TOLERANCE: 10%; Type: capacitor; VPC: 50V; Vendor: TDK
C6-C9 C24-C27 = PAS,CAP,NP: CCA: 42; DigiKey: 490-10749-1-ND; Family: passive; Index PN: 1719; Install: Y; Lead Style: SMT; MFG: Murata; P/D_NUM: GRM21BR61E226ME44L; Part Number: GRM21BR61E226ME44L; Part Specific: CAP CER 22UF 25V X5R 0805; Type: capacitor; VPC: 25V; Vendor: Murata
L1 = PAS,INDUCTOR,_large: DigiKey: SRN8040-6R8YCT-ND; Family: passive; Index PN: 1770; Lead Style: SMT; MFG: Bourns; P/D_NUM: SRN8040-6R8Y; Part Number: SRN8040-6R8Y; Part Specific: FIXED IND 6.8UH 3.9A 33 MOHM SMD; Type: inductor; VENDOR: Bourns; VPC: 4.9A
L11 = PAS,INDUCTOR,_large: DigiKey: SRN8040-3R6YCT-ND; Family: passive; Index PN: 1769; Lead Style: SMT; MFG: Bourns; P/D_NUM: SRN8040-3R6Y; Part Number: SRN8040-3R6Y; Part Specific: FIXED IND 3.6UH 4.9A 22 MOHM SMD; Type: inductor; VENDOR: Bourns; VPC: 4.9A
R1 R3 R29 = PAS,R,large: ALT_SYMBOLS: 0402_1mm; DigiKey: 541-100KLCT-ND; Family: passive; Index PN: 712; Lead Style: SMT; MFG: Vishay/Dale; Material: chip; P/D_NUM: CRCW0402100KFKED; Part Number: CRCW0402100KFKED; Part Specific: RES 100K OHM 1/10W 1% 0402 SMD; Power: 1/16W; TOLERANCE: 1%; Type: resistor; VENDOR: Vishay/Dale; VPC: 1/16W
R2 = PAS,R,large: ALT_SYMBOLS: 0402_1mm; DigiKey: P43.2KLCT-ND; Family: passive; Index PN: 1673; Lead Style: SMT; MFG: Panasonic; Material: chip; P/D_NUM: ERJ-2RKF4322X; Part Number: ERJ-2RKF4322X; Part Specific: RES 43.2K OHM 1% 1/10W 0402 SMD; TOLERANCE: 1%; Type: resistor; VENDOR: Panasonic; VPC: 1/10W
R30 = PAS,R,large: ALT_SYMBOLS: 0402_1mm; DigiKey: P43.2KLCT-ND; Family: passive; Index PN: 1673; Install: DNI; Lead Style: SMT; MFG: Panasonic; Material: chip; P/D_NUM: ERJ-2RKF4322X; Part Number: ERJ-2RKF4322X; Part Specific: RES 43.2K OHM 1% 1/10W 0402 SMD; TOLERANCE: 1%; Type: resistor; VENDOR: Panasonic; VPC: 1/10W
R31 = PAS,R,large: ALT_SYMBOLS: 0402_1mm; DigiKey: P0.0JCT-ND; Family: passive; Index PN: 687; Lead Style: SMT; MFG: Panasonic; Material: chip; P/D_NUM: ERJ-2GE0R00X; Part Number: ERJ-2GE0R00X; Part Specific: RES 0.0 OHM 1/16W 0402 SMD; Power: 1/16W; Type: resistor; VENDOR: Panasonic; VPC: 1/16W
TP1 TP10 = Testpoint: Test point; DigiKey: 36-5012-ND; Family: electro/mechanical; Index PN: 1162; Install: DNI; Lead Style: TH; MFG: Keystone; P/D_NUM: 5012; Part Number: 5012; Part Specific: TEST POINT PC MULTI PURPOSE WHT .063inD hole; Type: terminal; Vendor: Keystone
TP2 TP3 TP8 TP9 = EM,TERM,TESTPOINT: DigiKey: 36-5011-ND; Family: electro/mechanical; Index PN: 1161; Install: Y; Lead Style: TH; MFG: Keystone; P/D_NUM: 5011; Part Number: 5011; Part Specific: TEST POINT PC MULTI PURPOSE BLK .063inD hole; Type: terminal; Vendor: Keystone
U3 U6 = PWR,REG,LMR33630,HSOIC8,1x: DigiKey: 296-51355-1-ND; Family: power; Index PN: 1772; Lead Style: SMT; MFG: Texas Instruments; Part Specific: IC REG BUCK ADJUSTABLE 2A 400kHz 8SOPWR; Type: reg,switching; Vendor: Texas Instruments

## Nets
AVDD10: C13.1 C45.1 C53.1 C57.1 C62.1 L4.2 U5.36(AVDD10A) U5.42(AVDD10A) U5.51(AVDD10B) U5.57(AVDD10B)
DVDD10: C16.1 C58.1 C63.1 L6.2 U5.47(DVDD10A) U5.62(DVDD10B)
GND: C1.2 C3.1 C4.2 C5.2 C6.1 C7.1 C8.1 C9.1 C10.2 C11.2 C12.2 C13.2 C14.2 C15.2 C16.2 C17.2 C18.2 C19.2 C20.2 C21.2 C22.1 C23.1 C24.1 C25.1 C26.1 C27.1 C28.2 C29.2 C30.1 C32.2 C33.2 C34.2 C35.2 C36.2 C37.2 C38.2 C39.1 C40.2 C41.2 C42.2 C43.2 C44.2 C45.2 C46.2 C47.2 C48.2 C49.2 C50.2 C51.2 C52.2 C53.2 C54.2 C55.2 C56.2 C57.2 C58.2 C59.2 C60.2 C61.2 C62.2 C63.2 C64.2 C65.2 C66.2 C67.2 C68.2 C69.2 C70.2 C71.2 C72.2 C73.2 C74.2 C75.2 D2.3 D3.3 D4.1(CATHODE) J1.2 J1.5 J1.8 J1.11 J1.17 J1.20 J1.21 J1.22 J1.23 J2.2 J3.1 J3.4 J3.7 J3.10 J3.13 J3.16 J3.19 J3.22 J3.25 J3.28 J3.33 J3.37 J3.42 J3.44 J3.46 J3.47 J3.52(GND) J3.53(GND) J3.54(GND) J3.55(GND) J3.56(GND) J3.57(GND) J3.58(GND) J3.59(GND) J3.60(GND) J3.61(GND) J3.62(GND) J3.63(GND) R2.1(N1) R5.1(N1) R6.1(N1) R30.1(N1) R41.2(N2) R44.1(N1) R45.1(N1) TP2.1(P1) TP3.1(P1) TP8.1(P1) TP9.1(P1) U1.3(GND) U1.8(GND) U2.3(GND) U2.8(GND) U3.1(PGND) U3.9(PAD) U4.1(A0) U4.2(A1) U4.3(A2) U4.4(GND) U5.30(CDSENSE) U5.129(GND) U6.1(PGND) U6.9(PAD) Y1.2 Y1.4
P5V: J3.48 J3.49 J3.50 J3.51 R11.1(N1)
P5V_HDMI0: D1.3 R32.1(N1) R33.1(N1) R34.1(N1) U4.8(VCC)
PVCC10: C14.1 C44.1 C56.1 L5.2 U5.34(PVCC10A) U5.49(PVCC10B)
VCC33: C10.1 C46.1 C47.1 C54.1 C55.1 L3.2 U5.35(PVCC33A) U5.37(AVDD33A) U5.50(PVCC33B) U5.52(AVDD33B)
A_HTPDN: R20.2(N2) R27.2(N2) U5.90(A_HTPDN)
A_LOCKN: R21.2(N2) R28.2(N2) U5.91(A_LOCKN)
APVCC10: C18.1 C64.1 L8.2 U5.64(APVCC10)
APVCC33: C17.1 C61.1 L7.2 U5.63(APVCC33)
B_HTPDN: R43.2(N2) U5.92(B_HTPDN)
B_LOCKN: R42.2(N2) U5.93(B_LOCKN)
CBUS_HPD: R13.1(N1) U5.33(CBUS_HPD)
CEC: R14.1(N1) U5.31(CEC)
DDCSCL0: R15.1(N1) U5.28(DDCSCL0)
DDCSCL1: R8.2(N2) U5.24(DDCSCL1)
DDCSDA0: R16.1(N1) U5.27(DDCSDA0)
DDCSDA1: R9.2(N2) U5.23(DDCSDA1)
EDID_WP: J2.1 R32.2(N2) U4.7(WP)
ENTEST: R44.2(N2) U5.70(ENTEST)
FE_3D_LR: J3.31 R35.1(N1)
HDMI_0_VCC5: D1.1 J1.18 R4.2(N2) R7.1(N1)
HDMI_CEC: J3.29 R19.1(N1)
HTPDN: J3.27 R20.1(N1)
I2C_BUSY: J3.35 TP4.1(P1)
IIC0_SCL: J3.34 TP5.1(P1)
IIC0_SDA: J3.32 TP7.1(P1)
IIC1_SCL: J3.38 R17.1(N1)
IIC1_SDA: J3.36 R18.1(N1)
INT#_SCDT: R37.2(N2) R38.2(N2) U5.19(INT#_SCDT)
IVDD10: C12.1 C19.1 C33.1 C36.1 C38.1 C41.1 C42.1 C51.1 C52.1 C66.1 C68.1 C70.1 C72.1 C73.1 L12.2 U5.6(IVDD10) U5.12(IVDD10) U5.20(IVDD10) U5.26(IVDD10) U5.48(IVDD10) U5.68(IVDD10) U5.75(IVDD10) U5.82(IVDD10) U5.88(IVDD10) U5.96(IVDD10) U5.110(IVDD10) U5.121(IVDD10)
LOCKN: J3.26 R21.1(N1)
OVDD33: C11.1 C35.1 C37.1 C40.1 C43.1 C67.1 C69.1 C71.1 C74.1 L2.1 R23.1(N1) R27.1(N1) R28.1(N1) R36.1(N1) R37.1(N1) R39.1(N1) R40.1(N1) R42.1(N1) R43.1(N1) U5.3(OVDD1833) U5.11(OVDD1833) U5.17(OVDD33) U5.32(OVDD33) U5.67(OVDD1833) U5.76(OVDD1833) U5.85(OVDD1833) U5.95(OVDD1833)
P0_RX0N: J1.9 U2.4(D2+) U2.7(NC2) U5.40(P0_RX0N)
P0_RX0P: J1.7 U2.5(D2-) U2.6(NC1) U5.41(P0_RX0P)
P0_RX1N: J1.6 U1.1(D1+) U1.10(NC4) U5.43(P0_RX1N)
P0_RX1P: J1.4 U1.2(D1-) U1.9(NC3) U5.44(P0_RX1P)
P0_RX2N: J1.3 U1.4(D2+) U1.7(NC2) U5.45(P0_RX2N)
P0_RX2P: J1.1 U1.5(D2-) U1.6(NC1) U5.46(P0_RX2P)
P0_RXCN: J1.12 U2.1(D1+) U2.10(NC4) U5.38(P0_RXCN)
P0_RXCP: J1.10 U2.2(D1-) U2.9(NC3) U5.39(P0_RXCP)
P1P0V: C24.2 C25.2 C26.2 C27.2 L4.1 L5.1 L6.1 L8.1 L10.2 L11.1 L12.1 L13.2 R31.2(N2)
P1P0V_BOOT: C31.2 U6.7(BOOT)
P1P0V_FB: R30.2(N2) R31.1(N1) U6.5(FB)
P1P0V_PWRGOOD: R29.2(N2) TP10.1 U6.4(PG)
P1P0V_SW: C31.1 L11.2 U6.8(SW)
P1P0V_VCC: C32.1 R29.1(N1) U6.6(VCC)
P3P3V: C6.2 C7.2 C8.2 C9.2 L1.1 L2.2 L3.1 L7.1 L9.2 L14.2 R1.2(N2)
P3P3V_BOOT: C2.2 U3.7(BOOT)
P3P3V_FB: R1.1(N1) R2.2(N2) U3.5(FB)
P3P3V_PWRGOOD: R3.2(N2) TP1.1 U3.4(PG)
P3P3V_SW: C2.1 L1.2 U3.8(SW)
P3P3V_VCC: C1.1 R3.1(N1) U3.6(VCC)
P5P0V: C3.2 C4.1 C5.1 C28.1 C29.1 C30.2 D1.2 R8.1(N1) R9.1(N1) R11.2(N2) U3.2(VIN) U3.3(EN) U6.2(VIN) U6.3(EN)
PCADR: R23.2(N2) R45.2(N2) U5.69(PCADR)
PCSCL: R17.2(N2) R40.2(N2) U5.22(PCSCL)
PCSDA: R18.2(N2) R39.2(N2) U5.21(PCSDA)
R0PWR5V: R4.1(N1) R5.2(N2) U5.29(R0PWR5V)
R1PWR5V: R41.1(N1) U5.25(R1PWR5V)
RX_CEC: D3.1 J1.13 R14.2(N2) R19.2(N2)
RX_HPD0: D3.2 J1.19 R6.2(N2) R7.2(N2) R13.2(N2)
SATUS_INT: J3.39 R38.1(N1)
SCDT_3DR_EVODD: R35.2(N2) U5.124(SCDT_3DR_EVODD)
SCDT_DR5: R10.2(N2) U5.16(SCDT_DR~{5})
SCDT_DR5_LED: D4.2(ANODE) R10.1(N1)
SCL_HDMI0_DDC_CI: D2.2 J1.15 R15.2(N2) R33.2(N2) U4.6(SCL)
SDA_HDMI0_DDC_CI: D2.1 J1.16 R16.2(N2) R34.2(N2) U4.5(SDA)
SPI1_CLK: J3.45 R24.1(N1)
SPI1_CSZ_x: J3.40 R25.1(N1)
SPI1_SIMO: J3.41 R26.1(N1)
SPI1_SOMI: J3.43 R12.1(N1)
SPI_CLK: R24.2(N2) U5.77(SPI_CLK)
SPI_DI: R12.2(N2) U5.80(SPI_DI)
SPI_DO: R26.2(N2) U5.79(SPI_DO)
SPI_SS: R25.2(N2) U5.78(SPI_SS)
SYSRSTN: C39.2 R36.2(N2) U5.15(SYSRSTN)
TVCC33: C34.1 C75.1 L14.1 U5.122(TVCC33)
TX0N: J3.24 U5.119(VB0_TXL0N)
TX0P: J3.23 U5.118(VB0_TXL0P)
TX1N: J3.21 U5.117(VB0_TXL1N)
TX1P: J3.20 U5.116(VB0_TXL1P)
TX2N: J3.18 U5.114(VB0_TXL2N)
TX2P: J3.17 U5.113(VB0_TXL2P)
TX3N: J3.15 U5.112(VB0_TXL3N)
TX3P: J3.14 U5.111(VB0_TXL3P)
TX4N: J3.12 U5.108(VB0_TXL4N)
TX4P: J3.11 U5.107(VB0_TXL4P)
TX5N: J3.9 U5.106(VB0_TXL5N)
TX5P: J3.8 U5.105(VB0_TXL5P)
TX6N: J3.6 U5.103(VB0_TXL6N)
TX6P: J3.5 U5.102(VB0_TXL6P)
TX7N: J3.3 U5.101(VB0_TXL7N)
TX7P: J3.2 U5.100(VB0_TXL7P)
VBO_AVDD10: C15.1 C48.1 C59.1 L13.1 U5.104(VB0_AVDD10) U5.115(VB0_AVDD10)
VBO_PVCC10: C21.1 C49.1 C50.1 C65.1 L10.1 U5.97(VBO_PVCC10) U5.109(VB0_DVDD10) U5.120(VB0_DVDD10)
VBO_PVCC33: C20.1 C60.1 L9.1 U5.98(VB0_PVCC33)
Vx1_PROJ_ON: J3.30 TP6.1(P1)
XTALIN: C23.2 R22.1(N1) U5.66(XTALIN) Y1.3
XTALOUT: C22.2 R22.2(N2) U5.65(XTALOUT) Y1.1

Not connected (* = marked no-connect by the designer): J1 14*; U5 1(SPDIF_DL0)* 2(I2S0_DR0)* 4(I2S1_DL1)* 5(I2S2_DR1)* 7(I2S3_DL2)* 8(I2S4_DR2)* 9(I2S5_DL3)* 10(WS_DR3)* 13(SCK_DCLK)* 14(MCLK_DR4)* 18(ENVBUS#_DL5)* 53(P1_RCNX)* 54(P1_RXCP)* 55(P1_RX0N)* 56(P1_RX0P)* 58(P1_RX1N)* 59(P1_RX1P)* 60(P1_RX2N)* 61(P1_RX2P)* 71(GP0)* 72(GP1)* 73(GP2)* 74(GP3)* 81(GP4)* 83(GP5)* 84(GP6)* 86(GP7)* 87(GP8)* 89(GP9)* 94(GP10)* 99(NC)* 123(GP11)* 125(ENENODD_DL5)* 126(MUTE_DL4)* 127(DSD_DR5)* 128(GP12)*

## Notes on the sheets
sheet 1
- (C) COPYRIGHT 2020
         Texas Instruments
        All Rights Reserved
sheet 2
- COMPUTER GENERATED DRAWING - DO NOT REVISE MANUALLY
- REVISIONS
- REV
- DESCRIPTION
- DATE
- APPROVED
- A
- Initial Release
- 01/26/2021
- M. VEGA
- DLPC7540EVM Front-End Board
- Cadence Capture V.17.2
sheet 3
- Vx1 Processor
- (C) COPYRIGHT 2020
         Texas Instruments
        All Rights Reserved
sheet 4
- EDID EEPROM
- INSTALL JUMPER TO
  DISABLE WP
- Cable
  Insertion
  Direction
- DC Blocking caps are on
  the Formatter Board
- HDMI & Vx1 Connection
- (C) COPYRIGHT 2020
         Texas Instruments
        All Rights Reserved
sheet 5
- Max IOUT 1A
- Vfb=1.0V
- Max IOUT 1A
- Vfb=1.0V
- POWER
- (C) COPYRIGHT 2020
         Texas Instruments
        All Rights Reserved
sheet 6
- A
- - Initial Release
- (C) COPYRIGHT 2020
         Texas Instruments
        All Rights Reserved
